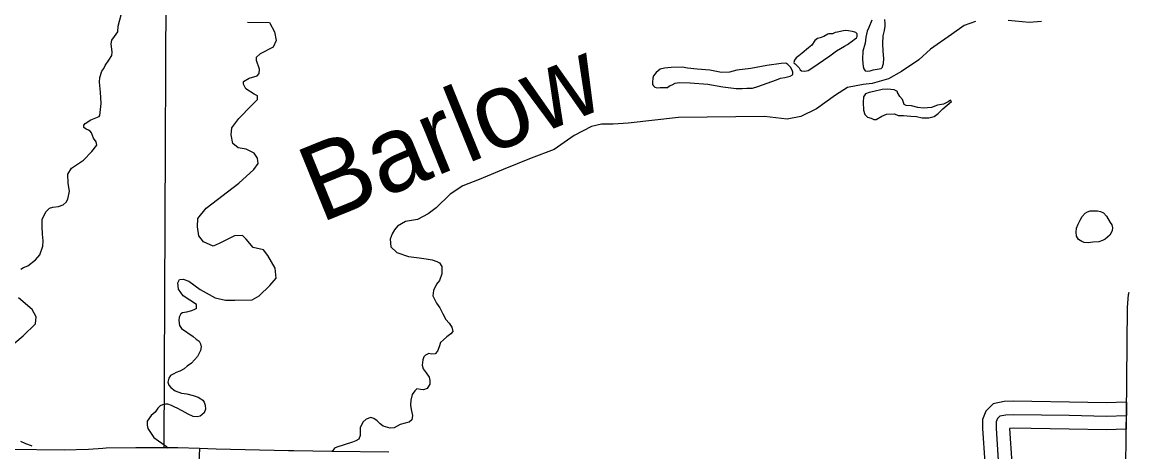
# Model space of a CAD drawing. Extents: x 61396 to 64680, y 55472 to 57605.
# Drawn here: x 62426.4 to 62618.7, y 56255.3 to 56330.1 of the extents above; entities that cross this region are included whole.
import ezdxf

# ---------------------------------------------------------------- set-up
doc = ezdxf.new("R2010")
doc.units = 0
for name, color, linetype in [('33', 7, 'Continuous'), ('35', 7, 'Continuous'), ('45', 7, 'Continuous'), ('5', 7, 'Continuous')]:
    doc.layers.add(name, color=color, linetype=linetype)

msp = doc.modelspace()

# ---------------------------------------------------------------- linework, layer by layer
at = {"layer": '33'}
for points in [[(62618.45, 56261.6), (62618.65, 56280.44), (62618.82, 56282.7), (62618.94, 56283.1)], [(62618.36, 56251.26), (62618.43, 56259.5), (62618.45, 56261.6)]]:
    msp.add_lwpolyline(points, dxfattribs=at)
at = {"layer": '35'}
for points in [[(62439.94, 56313.83), (62440.08, 56314.88), (62440.18, 56315.93), (62440.08, 56317.88), (62439.89, 56319.6), (62439.94, 56320.46), (62440.32, 56321.55), (62440.65, 56322.03), (62440.89, 56322.55), (62441.51, 56323.46), (62442.04, 56324.27), (62442.08, 56324.84), (62441.94, 56326.31), (62442.04, 56326.93), (62442.51, 56327.55), (62443.08, 56328.41), (62443.13, 56329.36), (62443.7, 56331.6)], [(62574.18, 56330.41), (62573.69, 56329.11), (62573.36, 56328.51), (62573.12, 56327.48), (62573, 56326.42), (62572.61, 56325.01), (62572.58, 56323.65), (62572.64, 56322.89), (62572.67, 56322.35), (62572.79, 56321.96), (62573, 56321.59), (62573.48, 56321.53), (62573.87, 56321.62), (62574.39, 56321.75), (62575.11, 56321.9), (62575.78, 56321.99), (62576.02, 56322.23), (62576.11, 56322.5), (62576.2, 56322.86), (62576.26, 56323.77), (62576.17, 56325.04), (62576.08, 56326.36), (62576.14, 56327.66), (62576.41, 56328.6), (62576.5, 56329.38), (62576.5, 56329.83), (62576.47, 56330.53)], [(62603.67, 56330.16), (62601.57, 56329.99), (62597.9, 56330.38)], [(62465.6, 56330.08), (62469.45, 56330.01), (62470.31, 56328.41), (62470.62, 56326.89), (62470.07, 56325.74), (62467.83, 56324.57)], [(62592.2, 56330.2), (62590.22, 56329.48), (62588.01, 56327.9), (62584.39, 56325.34), (62582.33, 56323.52), (62579.35, 56321.5), (62577.07, 56320.18), (62574.22, 56319.39), (62572.65, 56319.22), (62569.96, 56318.69), (62567.85, 56317.36), (62564.58, 56314.96), (62561.81, 56313.68), (62559.45, 56313.19), (62555.5, 56313.65), (62540.55, 56313.48), (62531.83, 56312.52), (62529.18, 56312.32), (62527.15, 56312.32), (62525.42, 56311.91), (62522.43, 56310.33), (62518.92, 56307.89), (62514.95, 56306.4), (62510.07, 56304.46), (62505.93, 56302.72), (62503.04, 56301.61), (62500.89, 56300.16), (62498.45, 56297.76), (62497.04, 56296.73), (62495.18, 56295.73), (62493.07, 56295.4), (62491.72, 56294.6), (62491.2, 56293.96), (62490.76, 56293.26), (62490.44, 56292.3), (62490.57, 56290.96), (62491.61, 56289.99), (62493.63, 56289.3), (62495.49, 56289.04), (62496.71, 56288.9), (62497.72, 56288.71), (62498.55, 56288.42), (62499.02, 56288.18), (62499.39, 56287.57), (62499.39, 56286.28), (62499.02, 56285.14), (62498.51, 56284.5), (62497.98, 56283.41), (62497.85, 56282.47), (62498.48, 56281.2), (62499.04, 56280.37), (62499.61, 56279.32), (62500.11, 56278.36), (62500.69, 56277.72), (62501.18, 56276.99), (62501.33, 56276.24), (62500.97, 56275.82), (62500.29, 56275.33), (62499.68, 56274.8), (62499.2, 56274.35), (62498.97, 56273.56), (62498.68, 56272.83), (62498.28, 56272.37), (62497.69, 56272.29), (62497.13, 56272.4), (62496.6, 56272.13), (62496.3, 56271.84), (62496.09, 56271.3), (62496, 56270.39), (62496.17, 56269.77), (62496.69, 56269.06), (62497.19, 56268.29), (62497.33, 56267.7), (62497.32, 56267.1), (62497.05, 56266.62), (62496.84, 56266.33), (62496.25, 56266.13), (62495.69, 56266.17), (62495.09, 56266.25), (62494.72, 56265.92), (62494.24, 56265.28), (62494.05, 56264.33), (62493.95, 56263.45), (62494.1, 56262.7), (62494.32, 56261.61), (62494.22, 56260.88), (62493.76, 56260.46)], [(62456.73, 56280.28), (62456.75, 56280.92), (62454.42, 56282.47), (62453.64, 56283.63), (62453.49, 56284.72), (62453.8, 56285.27), (62454.42, 56285.34), (62455.43, 56285.03), (62457.37, 56283.56), (62460.01, 56282.08), (62461.8, 56281.69), (62463.43, 56281.69), (62466.46, 56281.77), (62467.63, 56282.47), (62469.49, 56284.26), (62470.58, 56285.5), (62470.43, 56287.29), (62469.18, 56289.46), (62468.41, 56290.47), (62466.62, 56290.86), (62465.38, 56292.34), (62464.75, 56292.96), (62463.36, 56292.88), (62460.71, 56291.56), (62459.63, 56291.09), (62457.99, 56291.87), (62457.14, 56292.88), (62456.91, 56294.43), (62456.98, 56295.91), (62458.46, 56297.7), (62464.13, 56302.05), (62466.74, 56304.46), (62467.49, 56305.49), (62467.37, 56306.4), (62466.8, 56307.26), (62465.37, 56307.95), (62464, 56308.23), (62463.09, 56308.97), (62462.8, 56310.46), (62462.91, 56311.66), (62464.11, 56313.32), (62466.29, 56315.54), (62467.37, 56316.63), (62467.37, 56317.26), (62466.8, 56317.54), (62465.31, 56318.46), (62464.91, 56319.26), (62464.91, 56319.77), (62465.89, 56320.34), (62467.31, 56320.74), (62467.66, 56321.14), (62467.71, 56321.89), (62467.2, 56323.37), (62467.2, 56324), (62467.83, 56324.57)], [(62426.2, 56287.07), (62426.68, 56287.4), (62427.4, 56287.69), (62428.73, 56288.74), (62429.49, 56289.59), (62430.06, 56291.12), (62430.11, 56292.02), (62429.97, 56293.17), (62429.92, 56294.5), (62429.92, 56295.79), (62430.59, 56297.12), (62431.21, 56297.69), (62431.78, 56297.88), (62432.73, 56298.02), (62433.59, 56298.26), (62434.07, 56298.74), (62434.4, 56299.26), (62434.64, 56300.69), (62434.45, 56301.98), (62434.35, 56303.6), (62435.02, 56304.65), (62437.11, 56306.07), (62438.54, 56307.55), (62439.4, 56308.69), (62439.31, 56309.27), (62438.83, 56309.88), (62438.5, 56310.79), (62438.26, 56311.12), (62437.97, 56311.27), (62437.54, 56311.46), (62437.16, 56311.74), (62437.16, 56312.17), (62437.4, 56312.46), (62438.4, 56313.08), (62439.83, 56313.65), (62439.94, 56313.83)], [(62425.16, 56274.26), (62426.59, 56275.5), (62428.78, 56277.59), (62428.87, 56278.78), (62428.16, 56280.07), (62425.82, 56282.12)], [(62456.73, 56280.28), (62456.39, 56280.08), (62455.87, 56279.84), (62455.03, 56279.63), (62454.31, 56279.51), (62454.03, 56279.34), (62453.71, 56278.74), (62453.66, 56278.14), (62453.81, 56277.3), (62454.17, 56276.77), (62456.16, 56275.36), (62456.71, 56274.94), (62457.19, 56274.58), (62457.45, 56274.08), (62457.56, 56273.59), (62457.45, 56272.96), (62456.95, 56271.9), (62456.38, 56271.32), (62455.86, 56270.74), (62455.13, 56270.21), (62454.58, 56269.73), (62453.84, 56269.36), (62453.22, 56269.12), (62452.79, 56268.91), (62452.23, 56268.58), (62451.93, 56268.13), (62451.77, 56267.41), (62451.97, 56266.94), (62452.3, 56266.48), (62453.07, 56265.94), (62454.14, 56265.54), (62455.09, 56265.38), (62456.19, 56265.13), (62457.02, 56264.81)], [(62457.02, 56264.81), (62457.49, 56264.55), (62457.88, 56264.28), (62458.07, 56263.97), (62458.28, 56263.41), (62458.33, 56262.72), (62458.07, 56262.12), (62457.7, 56261.73), (62457.37, 56261.53), (62456.87, 56261.42), (62456.18, 56261.46), (62455.29, 56261.87), (62454.24, 56262.46), (62453.41, 56262.94), (62453, 56263.08), (62452.42, 56263.38), (62451.79, 56263.61), (62451.38, 56263.63), (62450.82, 56263.49), (62450.45, 56263.32), (62450.03, 56262.93), (62449.55, 56262.22), (62448.89, 56261.66), (62448.19, 56260.65), (62448.19, 56259.94), (62448.28, 56259.4), (62449.31, 56257.82), (62451.54, 56256.22), (62451.84, 56256.03)], [(62493.76, 56260.46), (62493.05, 56260.28), (62492.15, 56260.07), (62491.13, 56259.5), (62490.41, 56259.41), (62489.21, 56259.81), (62488.7, 56260.21), (62488.15, 56260.72), (62487.57, 56261.14), (62487.04, 56261.28), (62486.23, 56261.01), (62485.65, 56260.45), (62485.24, 56259.47), (62485.19, 56258.18), (62484.96, 56257.54), (62484.47, 56257.25), (62483.88, 56256.98), (62481.15, 56256.14), (62480.75, 56255.94), (62480.37, 56255.35)], [(62428.2, 56256.33), (62428.08, 56256.38), (62427.08, 56256.73), (62426.2, 56257.14)]]:
    msp.add_lwpolyline(points, dxfattribs=at)
for points in [[(62566.55, 56327.95), (62565.84, 56327.56), (62565.21, 56327.33), (62564.76, 56327.22), (62564.29, 56326.85), (62563.74, 56326.07), (62563.16, 56325.62), (62562.06, 56324.65), (62561.49, 56324.23), (62561.04, 56323.84), (62560.73, 56323.47), (62560.62, 56323.05), (62560.7, 56322.9), (62560.88, 56322.79), (62561.17, 56322.55), (62561.56, 56322.11), (62561.7, 56321.79), (62561.96, 56321.58), (62562.56, 56321.56), (62563.11, 56321.66), (62563.74, 56322.08), (62566.91, 56324.21), (62568.04, 56325.1), (62569.43, 56325.88), (62569.93, 56326.2), (62570.43, 56326.51), (62570.85, 56326.83), (62571.14, 56327.04), (62571.53, 56327.35), (62571.61, 56327.56), (62571.61, 56327.72), (62571.61, 56328.03), (62571.42, 56328.24), (62571.21, 56328.35), (62570.74, 56328.43), (62570.14, 56328.56), (62569.56, 56328.61), (62568.99, 56328.51), (62568.22, 56328.32), (62567.81, 56328.24), (62567.33, 56328.06), (62566.7, 56328.03)], [(62554.37, 56318.9), (62556, 56319.43), (62557.59, 56320.03), (62558.33, 56320.35), (62559.04, 56320.42), (62559.99, 56320.67), (62560.38, 56320.92), (62560.42, 56320.99), (62560.45, 56321.34), (62560.35, 56321.7), (62560.03, 56322.26), (62559.6, 56322.72), (62559.22, 56322.93), (62558.4, 56322.9), (62555.92, 56322.55), (62553.16, 56321.98), (62550.72, 56321.73), (62549.45, 56321.38), (62548.03, 56321.31), (62546.02, 56321.7), (62543.79, 56321.91), (62542.16, 56322.09), (62541.24, 56322.23), (62539.3, 56322.16), (62538.16, 56322.09), (62537.38, 56321.87), (62536.71, 56321.31), (62536.22, 56320.71), (62536.08, 56320.32), (62536.04, 56319.61), (62536.04, 56319.22), (62536.22, 56318.97), (62536.46, 56318.76), (62536.85, 56318.62), (62537.38, 56318.72), (62537.92, 56318.72), (62538.66, 56318.72), (62538.98, 56318.97), (62539.47, 56319.18), (62540, 56319.43), (62540.68, 56319.57), (62542.62, 56319.5), (62545.66, 56319.29), (62548.25, 56318.83), (62550.58, 56318.55), (62551.61, 56318.55), (62552.46, 56318.58), (62553.45, 56318.58)], [(62578.67, 56318.03), (62578.05, 56318.29), (62576.91, 56318.39), (62575.98, 56318.34), (62574.53, 56318.03), (62573.7, 56317.82), (62573.08, 56317.62), (62572.72, 56317.05), (62572.67, 56316.12), (62572.72, 56314.77), (62572.98, 56314), (62573.45, 56313.53), (62574.07, 56313.38), (62574.53, 56313.12), (62574.95, 56313.12), (62575.93, 56313.69), (62576.75, 56314.05), (62578.1, 56314.1), (62578.77, 56313.84), (62579.7, 56313.84), (62580.99, 56313.69), (62581.98, 56313.64), (62582.96, 56313.43), (62584.1, 56313.43), (62585.03, 56313.64), (62585.7, 56314.15), (62586.53, 56314.98), (62588.03, 56316.27), (62587.87, 56316.48), (62587.46, 56316.22), (62586.63, 56315.81), (62585.6, 56315.6), (62584.56, 56315.19), (62583.17, 56315.13), (62582.18, 56315.24), (62581.1, 56315.5), (62580.17, 56315.55), (62579.81, 56315.75), (62579.49, 56316.63), (62579.03, 56317.15), (62578.67, 56317.82)], [(62611.68, 56297.07), (62612.15, 56297.25), (62612.61, 56297.27), (62613.45, 56297.27), (62613.97, 56297.15), (62614.44, 56296.88), (62615.01, 56296.33), (62615.62, 56295.22), (62615.92, 56294.78), (62616.04, 56294.31), (62615.99, 56293.82), (62615.82, 56293.4), (62615.55, 56293.03), (62615.16, 56292.66), (62614.76, 56292.34), (62614.32, 56292.07), (62613.65, 56291.84), (62612.61, 56291.79), (62611.78, 56291.67), (62611.11, 56291.75), (62610.72, 56291.92), (62610.15, 56292.26), (62609.78, 56292.86), (62609.7, 56293.52), (62609.78, 56294.24), (62610.07, 56294.95), (62610.39, 56295.59), (62610.76, 56296.28), (62611.26, 56296.85)]]:
    msp.add_lwpolyline(points, close=True, dxfattribs=at)
at = {"layer": '45'}
for p, q in [((62618.47, 56263.95), (62618.43, 56259.26)), ((62457.25, 56255.88), (62457.06, 56251.2))]:
    msp.add_line(p, q, dxfattribs=at)
for points in [[(62601.99, 56264.07), (62598.83, 56264.12), (62597.22, 56264.05), (62595.3, 56263.69), (62594.02, 56262.4), (62593.45, 56260.95), (62593.45, 56259.36), (62593.82, 56253.47)], [(62618.47, 56263.95), (62614.92, 56263.83), (62608.55, 56263.96), (62601.99, 56264.07)], [(62618.45, 56261.6), (62614.93, 56261.48), (62608.51, 56261.62), (62598.86, 56261.78), (62597.49, 56261.71), (62596.45, 56261.52), (62596.02, 56261.09), (62595.8, 56260.51), (62595.8, 56259.43), (62596.32, 56251.01)], [(62601.91, 56259.38), (62598.9, 56259.43), (62598.15, 56259.4), (62598.53, 56253.32)], [(62618.43, 56259.26), (62614.95, 56259.14), (62608.47, 56259.27), (62601.91, 56259.38)], [(62440.48, 56255.9), (62437.97, 56255.71), (62433.76, 56255.63), (62424.2, 56255.75)], [(62457.25, 56255.88), (62453.5, 56256.03), (62446.2, 56256.03), (62441.02, 56255.94), (62440.48, 56255.9)], [(62473.69, 56255.47), (62472.73, 56255.49), (62460.16, 56255.76), (62457.25, 56255.88)], [(62490.17, 56255.26), (62480.3, 56255.35), (62473.69, 56255.47)]]:
    msp.add_lwpolyline(points, dxfattribs=at)
at = {"layer": '5'}
msp.add_lwpolyline([(62451.61, 56374.62), (62451.08, 56256.03)], dxfattribs=at)

# ---------------------------------------------------------------- texts
at = {"layer": '35'}
msp.add_text('Barlow', height=13.2, rotation=22.0912, dxfattribs=at).set_placement((62478.29, 56295.08))

doc.saveas('drawing.dxf')
